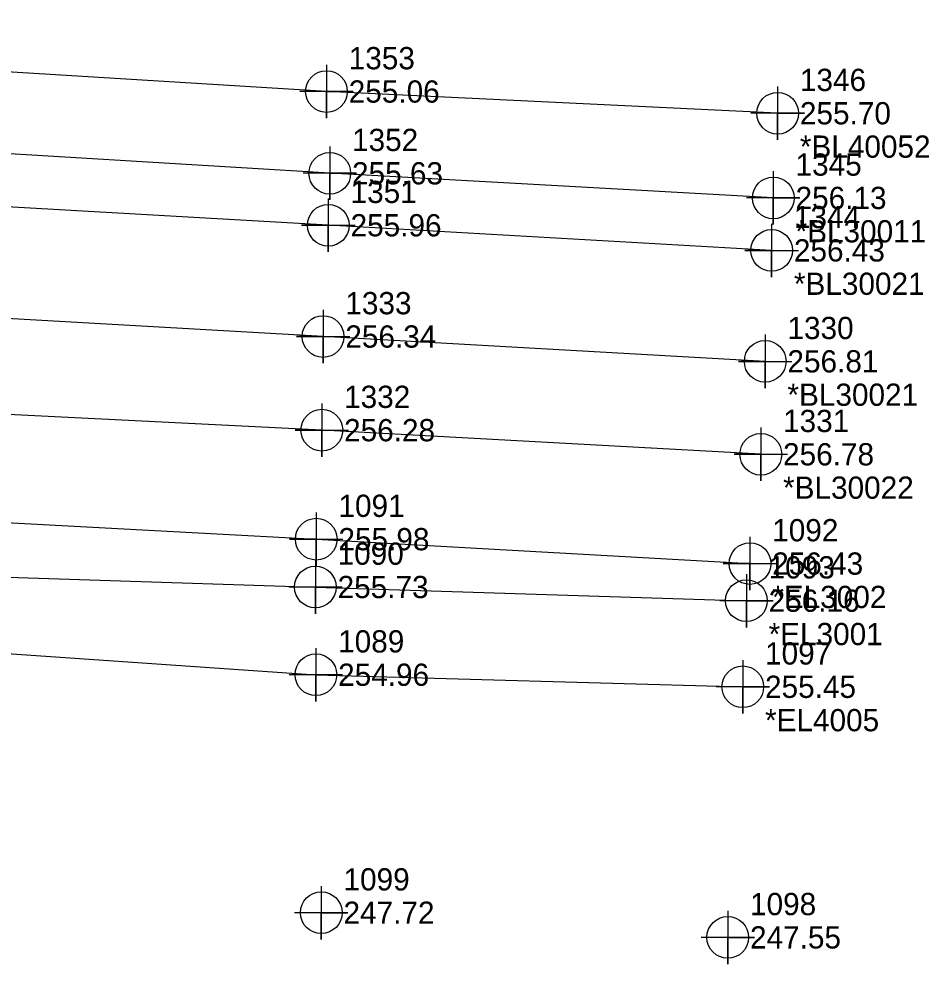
# Model space of a CAD drawing. Extents: x 2130962 to 2131465, y 643052 to 644206.
# Drawn here: x 2131362.5 to 2131464.7, y 643103.4 to 643209.7 of the extents above; entities that cross this region are included whole.
import ezdxf

# ---------------------------------------------------------------- set-up
doc = ezdxf.new("R2010")
doc.units = 0
for name, color, linetype in [('Exist DTM Breakline', 7, 'Continuous'), ('Exist DTM Breakline Cogo Comment', 7, 'Continuous'), ('Exist DTM Breakline Cogo Elevation', 7, 'Continuous'), ('Exist DTM Breakline Cogo Number', 7, 'Continuous'), ('Exist DTM Breakline Cogo Point CELL', 7, 'Continuous'), ('Exist DTM Regular Point CELL', 7, 'Continuous'), ('Exist DTM Regular Point Cogo Elevation', 7, 'Continuous'), ('Exist DTM Regular Point Cogo Number', 7, 'Continuous'), ('Exist Roads EOP', 7, 'Continuous'), ('Exist Roads EOP Cogo Comment', 7, 'Continuous'), ('Exist Roads EOP Cogo Elevation', 7, 'Continuous'), ('Exist Roads EOP Cogo Number', 7, 'Continuous'), ('Exist Roads EOP Cogo Point CELL', 7, 'Continuous'), ('Exist Roads EOT', 7, 'Continuous'), ('Exist Roads EOT Cogo Comment', 7, 'Continuous'), ('Exist Roads EOT Cogo Elevation', 7, 'Continuous'), ('Exist Roads EOT Cogo Number', 7, 'Continuous'), ('Exist Roads EOT Cogo Point CELL', 7, 'Continuous')]:
    doc.layers.add(name, color=color, linetype=linetype)

msp = doc.modelspace()

# ---------------------------------------------------------------- linework, layer by layer
at = {"layer": 'Exist DTM Breakline'}
for p, q in [((2131313.0171, 643141.6555), (2131395.8335, 643135.9257)), ((2131395.8335, 643135.9257), (2131443.8097, 643134.5681))]:
    msp.add_line(p, q, dxfattribs=at)
msp.add_lwpolyline([(2131447.7276, 643199.0466), (2131397.0228, 643201.4878), (2131347.6587, 643204.5248), (2131290.3074, 643209.6518)], dxfattribs=at)
at = {"layer": 'Exist DTM Breakline Cogo Point CELL'}
for points in [[(2131397.0228, 643204.4878), (2131397.0228, 643198.4878), (2131397.0228, 643201.4878), (2131400.0228, 643201.4878), (2131394.0228, 643201.4878)], [(2131447.7276, 643202.0466), (2131447.7276, 643196.0466), (2131447.7276, 643199.0466), (2131450.7276, 643199.0466), (2131444.7276, 643199.0466)], [(2131395.8335, 643138.9257), (2131395.8335, 643132.9257), (2131395.8335, 643135.9257), (2131398.8335, 643135.9257), (2131392.8335, 643135.9257)], [(2131443.8097, 643137.5681), (2131443.8097, 643131.5681), (2131443.8097, 643134.5681), (2131446.8097, 643134.5681), (2131440.8097, 643134.5681)]]:
    msp.add_lwpolyline(points, dxfattribs=at)
for centre in [(2131397.0228, 643201.4878), (2131447.7276, 643199.0466), (2131395.8335, 643135.9257), (2131443.8097, 643134.5681)]:
    msp.add_circle(centre, 2.344, dxfattribs=at)
at = {"layer": 'Exist DTM Regular Point CELL'}
for points in [[(2131396.4383, 643112.1717), (2131396.4383, 643106.1717), (2131396.4383, 643109.1717), (2131399.4383, 643109.1717), (2131393.4383, 643109.1717)], [(2131442.1207, 643109.3944), (2131442.1207, 643103.3944), (2131442.1207, 643106.3944), (2131445.1207, 643106.3944), (2131439.1207, 643106.3944)]]:
    msp.add_lwpolyline(points, dxfattribs=at)
for centre in [(2131396.4383, 643109.1717), (2131442.1207, 643106.3944)]:
    msp.add_circle(centre, 2.344, dxfattribs=at)
at = {"layer": 'Exist Roads EOP'}
for points in [[(2131447.2378, 643189.5276), (2131397.3957, 643192.2966), (2131347.7242, 643195.3218), (2131298.3748, 643197.6139), (2131274.5841, 643203.5275)], [(2131280.8132, 643131.5166), (2131296.9579, 643145.3867), (2131345.0473, 643147.4189), (2131395.7747, 643145.7863), (2131444.2123, 643144.2465)]]:
    msp.add_lwpolyline(points, dxfattribs=at)
at = {"layer": 'Exist Roads EOP Cogo Point CELL'}
for points in [[(2131397.3957, 643195.2966), (2131397.3957, 643189.2966), (2131397.3957, 643192.2966), (2131400.3957, 643192.2966), (2131394.3957, 643192.2966)], [(2131447.2378, 643192.5276), (2131447.2378, 643186.5276), (2131447.2378, 643189.5276), (2131450.2378, 643189.5276), (2131444.2378, 643189.5276)], [(2131395.7747, 643148.7863), (2131395.7747, 643142.7863), (2131395.7747, 643145.7863), (2131398.7747, 643145.7863), (2131392.7747, 643145.7863)], [(2131444.2123, 643147.2465), (2131444.2123, 643141.2465), (2131444.2123, 643144.2465), (2131447.2123, 643144.2465), (2131441.2123, 643144.2465)]]:
    msp.add_lwpolyline(points, dxfattribs=at)
for centre in [(2131397.3957, 643192.2966), (2131447.2378, 643189.5276), (2131395.7747, 643145.7863), (2131444.2123, 643144.2465)]:
    msp.add_circle(centre, 2.344, dxfattribs=at)
at = {"layer": 'Exist Roads EOT'}
msp.add_line((2131395.87, 643151.1658), (2131444.617, 643148.4219), dxfattribs=at)
for points in [[(2131447.0543, 643183.628), (2131397.23, 643186.4537), (2131347.2728, 643189.3277), (2131297.7395, 643192.2318), (2131269.1537, 643194.0491)], [(2131446.3277, 643171.1555), (2131396.6439, 643173.9458), (2131346.5769, 643176.7932), (2131297.2277, 643179.6845)], [(2131445.8347, 643160.7067), (2131396.5039, 643163.4177), (2131346.2151, 643165.9442), (2131310.8065, 643167.8349)], [(2131296.63, 643156.5688), (2131345.6305, 643153.8593), (2131395.87, 643151.1658)]]:
    msp.add_lwpolyline(points, dxfattribs=at)
at = {"layer": 'Exist Roads EOT Cogo Point CELL'}
for points in [[(2131397.23, 643189.4537), (2131397.23, 643183.4537), (2131397.23, 643186.4537), (2131394.23, 643186.4537), (2131400.23, 643186.4537)], [(2131447.0543, 643186.628), (2131447.0543, 643180.628), (2131447.0543, 643183.628), (2131444.0543, 643183.628), (2131450.0543, 643183.628)], [(2131396.6439, 643176.9458), (2131396.6439, 643170.9458), (2131396.6439, 643173.9458), (2131393.6439, 643173.9458), (2131399.6439, 643173.9458)], [(2131446.3277, 643174.1555), (2131446.3277, 643168.1555), (2131446.3277, 643171.1555), (2131443.3277, 643171.1555), (2131449.3277, 643171.1555)], [(2131396.5039, 643166.4177), (2131396.5039, 643160.4177), (2131396.5039, 643163.4177), (2131393.5039, 643163.4177), (2131399.5039, 643163.4177)], [(2131445.8347, 643163.7067), (2131445.8347, 643157.7067), (2131445.8347, 643160.7067), (2131442.8347, 643160.7067), (2131448.8347, 643160.7067)], [(2131395.87, 643154.1658), (2131395.87, 643148.1658), (2131395.87, 643151.1658), (2131392.87, 643151.1658), (2131398.87, 643151.1658)], [(2131444.617, 643151.4219), (2131444.617, 643145.4219), (2131444.617, 643148.4219), (2131441.617, 643148.4219), (2131447.617, 643148.4219)]]:
    msp.add_lwpolyline(points, dxfattribs=at)
for centre in [(2131397.23, 643186.4537), (2131447.0543, 643183.628), (2131396.6439, 643173.9458), (2131446.3277, 643171.1555), (2131396.5039, 643163.4177), (2131445.8347, 643160.7067), (2131395.87, 643151.1658), (2131444.617, 643148.4219)]:
    msp.add_circle(centre, 2.344, dxfattribs=at)

# ---------------------------------------------------------------- texts
at = {"layer": 'Exist DTM Breakline Cogo Comment'}
for s, p in [('*BL40052', (2131450.2276, 643194.0466)), ('*EL4005', (2131446.3097, 643129.5681))]:
    msp.add_text(s, height=2.5, dxfattribs=at).set_placement(p)
at = {"layer": 'Exist DTM Breakline Cogo Elevation'}
for s, p in [('255.06', (2131399.5228, 643200.2378)), ('255.70', (2131450.2276, 643197.7966)), ('254.96', (2131398.3335, 643134.6757)), ('255.45', (2131446.3097, 643133.3181))]:
    msp.add_text(s, height=2.5, dxfattribs=at).set_placement(p)
at = {"layer": 'Exist DTM Breakline Cogo Number'}
for s, p in [('1353', (2131399.5228, 643203.9878)), ('1346', (2131450.2276, 643201.5466)), ('1089', (2131398.3335, 643138.4257)), ('1097', (2131446.3097, 643137.0681))]:
    msp.add_text(s, height=2.5, dxfattribs=at).set_placement(p)
at = {"layer": 'Exist DTM Regular Point Cogo Elevation'}
for s, p in [('247.72', (2131398.9383, 643107.9217)), ('247.55', (2131444.6207, 643105.1444))]:
    msp.add_text(s, height=2.5, dxfattribs=at).set_placement(p)
at = {"layer": 'Exist DTM Regular Point Cogo Number'}
for s, p in [('1099', (2131398.9383, 643111.6717)), ('1098', (2131444.6207, 643108.8944))]:
    msp.add_text(s, height=2.5, dxfattribs=at).set_placement(p)
at = {"layer": 'Exist Roads EOP Cogo Comment'}
for s, p in [('*BL30011', (2131449.7378, 643184.5276)), ('*EL3001', (2131446.7123, 643139.2465))]:
    msp.add_text(s, height=2.5, dxfattribs=at).set_placement(p)
at = {"layer": 'Exist Roads EOP Cogo Elevation'}
for s, p in [('255.63', (2131399.8957, 643191.0466)), ('256.13', (2131449.7378, 643188.2776)), ('255.73', (2131398.2747, 643144.5363)), ('256.16', (2131446.7123, 643142.9965))]:
    msp.add_text(s, height=2.5, dxfattribs=at).set_placement(p)
at = {"layer": 'Exist Roads EOP Cogo Number'}
for s, p in [('1352', (2131399.8957, 643194.7966)), ('1345', (2131449.7378, 643192.0276)), ('1090', (2131398.2747, 643148.2863)), ('1093', (2131446.7123, 643146.7465))]:
    msp.add_text(s, height=2.5, dxfattribs=at).set_placement(p)
at = {"layer": 'Exist Roads EOT Cogo Comment'}
for s, p in [('*BL30021', (2131449.5543, 643178.628)), ('*BL30021', (2131448.8277, 643166.1555)), ('*BL30022', (2131448.3347, 643155.7067)), ('*EL3002', (2131447.117, 643143.4219))]:
    msp.add_text(s, height=2.5, dxfattribs=at).set_placement(p)
at = {"layer": 'Exist Roads EOT Cogo Elevation'}
for s, p in [('255.96', (2131399.73, 643185.2037)), ('256.43', (2131449.5543, 643182.378)), ('256.34', (2131399.1439, 643172.6958)), ('256.81', (2131448.8277, 643169.9055)), ('256.28', (2131399.0039, 643162.1677)), ('256.78', (2131448.3347, 643159.4567)), ('255.98', (2131398.37, 643149.9158)), ('256.43', (2131447.117, 643147.1719))]:
    msp.add_text(s, height=2.5, dxfattribs=at).set_placement(p)
at = {"layer": 'Exist Roads EOT Cogo Number'}
for s, p in [('1351', (2131399.73, 643188.9537)), ('1344', (2131449.5543, 643186.128)), ('1333', (2131399.1439, 643176.4458)), ('1330', (2131448.8277, 643173.6555)), ('1332', (2131399.0039, 643165.9177)), ('1331', (2131448.3347, 643163.2067)), ('1091', (2131398.37, 643153.6658)), ('1092', (2131447.117, 643150.9219))]:
    msp.add_text(s, height=2.5, dxfattribs=at).set_placement(p)

doc.saveas('drawing.dxf')
